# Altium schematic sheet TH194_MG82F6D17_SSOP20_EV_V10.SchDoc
size 284 x 195 mm
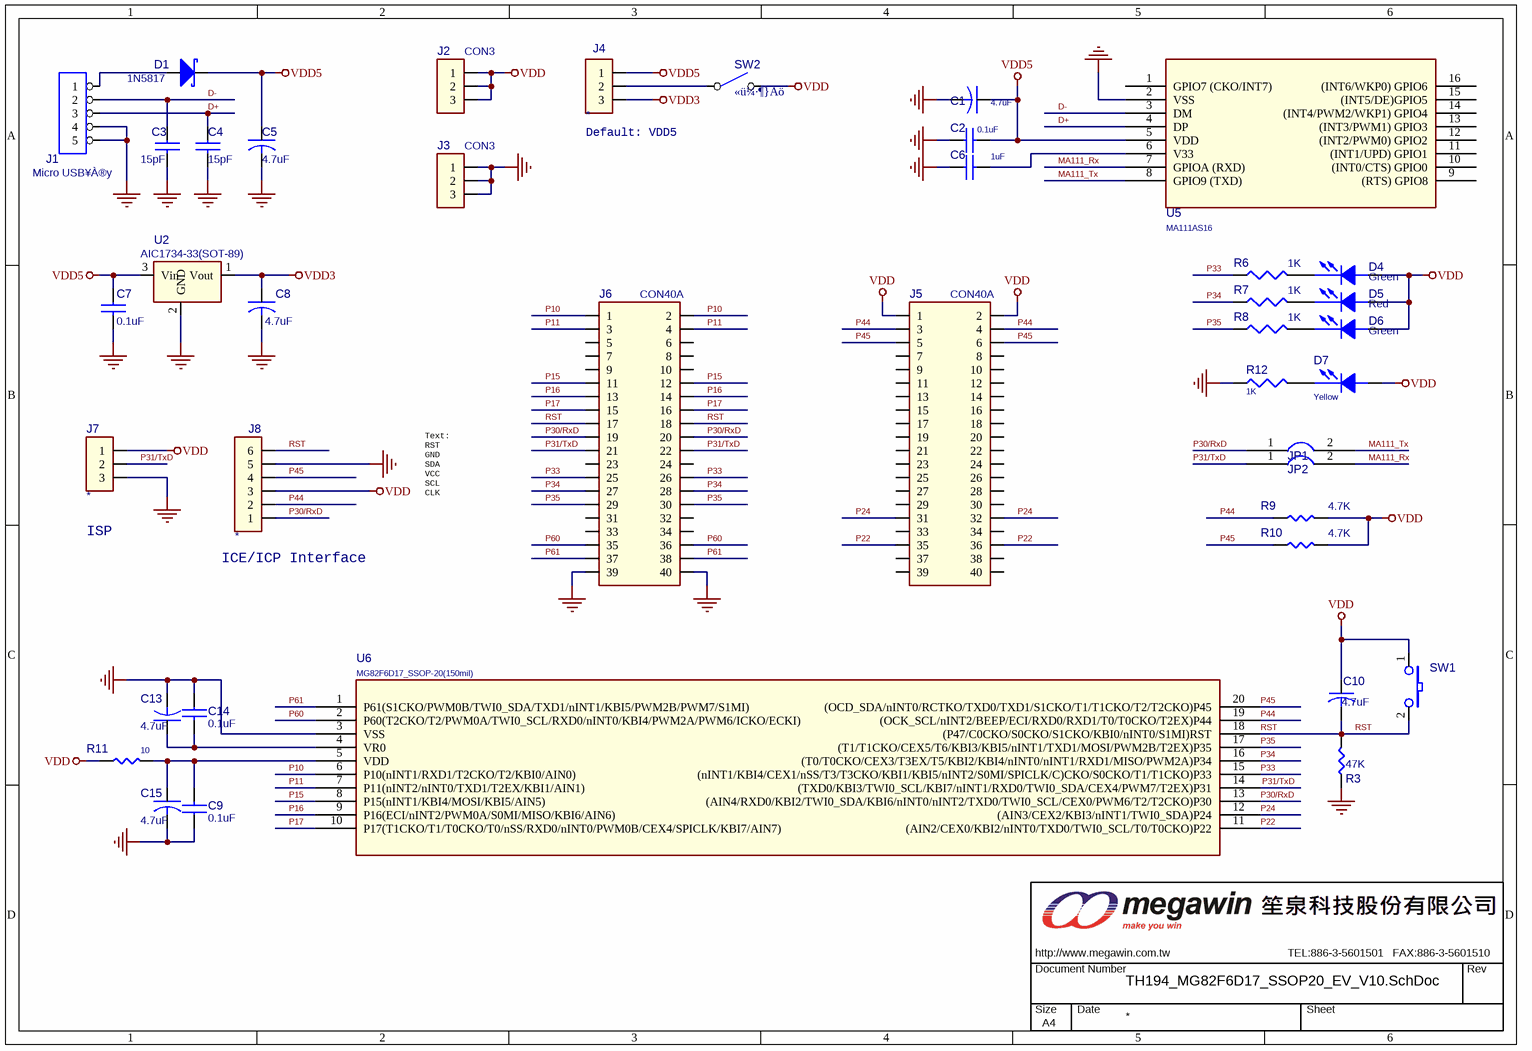
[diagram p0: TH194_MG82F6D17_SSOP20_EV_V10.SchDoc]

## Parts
C1  4.7uF  [0805C]
C2  0.1uF  [0805C]
C3  15pF  [0805C]
C4  15pF  [0805C]
C5  4.7uF  [1206C]
C6  1uF  [0805C]
C7  0.1uF  [0805C]
C8  4.7uF  [0805C]
C9  0.1uF  [0805C]
C10  4.7uF  [0805C]
C13  4.7uF  [0805C]
C14  0.1uF  [0805C]
C15  4.7uF  [0805C]
D1  1N5817  [D5817_SMD_1]
D4  Green  [0805D]
D5  Red  [0805D]
D6  Green  [0805D]
D7  Yellow  [0805D]
J1  Micro USB¥À®y  [JACK_USB_SMD290X220P065]
J2  CON3  [PS3P254]
J3  CON3  [PS3P254]
J4  *  [JUMP3_SMD]
J5  CON40A  [PS20X2P254]
J6  CON40A  [PS20X2P254]
J7  *  [PS3P254f_90]
J8  *  [PS6P254F_90]
JP1  JUMPER2  [PS2P254]  (value not drawn)
JP2  JUMPER2  [PS2P254]  (value not drawn)
MW1  OrgAddr3: TEL:886-3-5601501   FAX:886-3-5601510  Page Size: A4  [MEGAWIN10_1]  (hidden comment: MW-A4)  (graphical)
R3  47K  [0805R]
R6  1K  [0805R]
R7  1K  [0805R]
R8  1K  [0805R]
R9  4.7K  [0805R]
R10  4.7K  [0805R]
R11  10  [0805R]
R12  1K  [0805R]
SW1  SW TACT-SPST  [SW_T_2P]  (value not drawn)
SW2  «ü¼·¶}Ãö  [DIP2_SW]
U2  AIC1734-33(SOT-89)  [SOT89]
U5  MA111AS16  [SO16_150P127]
U6  MG82F6D17_SSOP-20(150mil)  [SSOP20_150P0635]

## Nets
GND_POWER: C1.2 C2.1 C3.2 C4.2 C5.2 C6.1 C7.2 C8.2 C9.1 C13.2 C14.1 C15.2 J1.4 J1.5 J3.1 J3.2 J3.3 J6.39 J6.40 J7.3 J8.5 R3.1 R12.1 U2.2(GND) U5.2(VSS) U6.3(VSS)
VDD: C10.1(POS) D4.1(ANODE) D5.1(ANODE) D6.1(ANODE) D7.1(ANODE) J2.1 J2.2 J2.3 J5.1 J5.2 J7.1 J8.3 R9.2 R10.2 R11.1 SW1.1 SW2.2(NO)
VDD3: C8.1 J4.3 U2.1(Vout)
VDD5: C1.1 C2.2 C5.1 C7.1 D1.2(K) J4.1 U2.3(Vin) U5.5(VDD)
D+: C4.1 J1.3 U5.4(DP)
D-: C3.1 J1.2 U5.3(DM)
MA111_Rx: JP2.2 U5.7(GPIOA_(RXD))
MA111_Tx: JP1.2 U5.8(GPIO9_(TXD))
P10: J6.1 J6.2 U6.6(P10(nINT1/RXD1/T2CKO/T2/KBI0/AIN0))
P11: J6.3 J6.4 U6.7(P11(nINT2/nINT0/TXD1/T2EX/KBI1/AIN1))
P15: J6.11 J6.12 U6.8(P15(nINT1/KBI4/MOSI/KBI5/AIN5))
P16: J6.13 J6.14 U6.9(P16(ECI/nINT2/PWM0A/S0MI/MISO/KBI6/AIN6))
P17: J6.15 J6.16 U6.10(P17(T1CKO/T1/T0CKO/T0/nSS/RXD0/nINT0/PWM0B/CEX4/SPICLK/KBI7/AIN7))
P22: J5.35 J5.36 U6.11((AIN2/CEX0/KBI2/nINT0/TXD0/TWI0_SCL/T0/T0CKO)P22)
P24: J5.31 J5.32 U6.12((AIN3/CEX2/KBI3/nINT1/TWI0_SDA)P24)
P30/RxD: J6.19 J6.20 J8.1 JP1.1 U6.13((AIN4/RXD0/KBI2/TWI0_SDA/KBI6/nINT0/nINT2/TXD0/TWI0_SCL/CEX0/PWM6/T2/T2CKO)P30)
P31/TxD: J6.21 J6.22 J7.2 JP2.1 U6.14((TXD0/KBI3/TWI0_SCL/KBI7/nINT1/RXD0/TWI0_SDA/CEX4/PWM7/T2EX)P31)
P33: J6.25 J6.26 R6.1 U6.15((nINT1/KBI4/CEX1/nSS/T3/T3CKO/KBI1/KBI5/nINT2/S0MI/SPICLK/C)CKO/S0CKO/T1/T1CKO)P33)
P34: J6.27 J6.28 R7.1 U6.16((T0/T0CKO/CEX3/T3EX/T5/KBI2/KBI4/nINT0/nINT1/RXD1/MISO/PWM2A)P34)
P35: J6.29 J6.30 R8.1 U6.17((T1/T1CKO/CEX5/T6/KBI3/KBI5/nINT1/TXD1/MOSI/PWM2B/T2EX)P35)
P44: J5.3 J5.4 J8.2 R9.1 U6.19((OCK_SCL/nINT2/BEEP/ECI/RXD0/RXD1/T0/T0CKO/T2EX)P44)
P45: J5.5 J5.6 J8.4 R10.1 U6.20((OCD_SDA/nINT0/RCTKO/TXD0/TXD1/S1CKO/T1/T1CKO/T2/T2CKO)P45)
P60: J6.35 J6.36 U6.2(P60(T2CKO/T2/PWM0A/TWI0_SCL/RXD0/nINT0/KBI4/PWM2A/PWM6/ICKO/ECKI))
P61: J6.37 J6.38 U6.1(P61(S1CKO/PWM0B/TWI0_SDA/TXD1/nINT1/KBI5/PWM2B/PWM7/S1MI))
RST: C10.2(NEG) J6.17 J6.18 J8.6 R3.2 SW1.2 U6.18((P47/C0CKO/S0CKO/S1CKO/KBI0/nINT0/S1MI)RST)
NetC6_2: C6.2 U5.6(V33)
NetC9_2: C9.2 C15.1 R11.2 U6.5(VDD)
NetC13_1: C13.1 C14.2 U6.4(VR0)
NetD1_1: D1.1(A) J1.1
NetD4_2: D4.2(CATHODE) R6.2
NetD5_2: D5.2(CATHODE) R7.2
NetD6_2: D6.2(CATHODE) R8.2
NetD7_2: D7.2(CATHODE) R12.2
NetJ4_2: J4.2 SW2.1(COMMON)

Not connected (* = marked no-connect by the designer): J5 7 8 9 10 11 12 13 14 15 16 17 18 19 20 21 22 23 24 25 26 27 28 29 30 33 34 37 38 39 40; J6 5 6 7 8 9 10 23 24 31 32 33 34; U5 1(GPIO7_(CKO/INT7)) 9((RTS)_GPIO8) 10((INT0/CTS)_GPIO0) 11((INT1/UPD)_GPIO1) 12((INT2/PWM0)_GPIO2) 13((INT3/PWM1)_GPIO3) 14((INT4/PWM2/WKP1)_GPIO4) 15((INT5/DE)GPIO5) 16((INT6/WKP0)_GPIO6)

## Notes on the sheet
- (near J4) Default: VDD5
- (near J7) ISP
- (near J8) ICE/ICP Interface
- Text:
  RST
  GND
  SDA
  VCC
  SCL
  CLK

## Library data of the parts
C1 C5 C8 C13 C15 = CAP
C2-C4 C6 C7 C9 C14 = CAP NP
C10 = C
D1 = DIODE_ZD: Schottky Diode
D4-D7 = LED
J1 = CON5: Connector
J4 J7 = CON3
J8 = CON6
MW1 = MW_A4_1
R3 R9-R11 = R
R6-R8 R12 = R_Dup1
SW2 = SW-2
U2 = AIC1734-33(SOT-89)_0
U6 = MG82G6D17_SSOP-20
